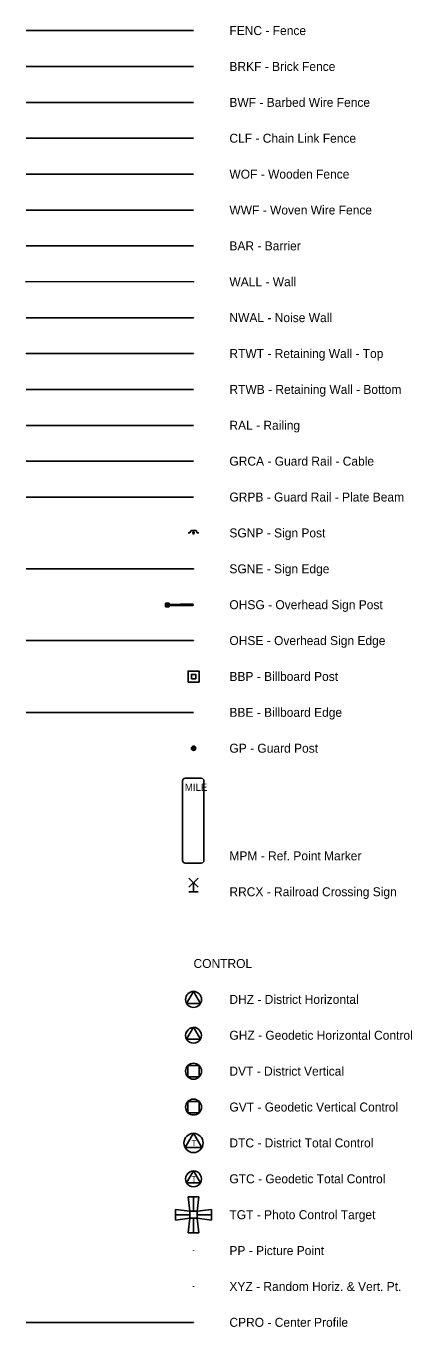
# Model space of a CAD drawing. Extents: x 2147712 to 2176316, y 2125036 to 2131746.
# Drawn here: x 2175974 to 2176297, y 2128230 to 2129318 of the extents above; entities that cross this region are included whole.
import ezdxf

# ---------------------------------------------------------------- set-up
doc = ezdxf.new("R2010")
doc.units = 0
for name, color, linetype in [('Default', 7, 'Continuous'), ('HORZ CTRL', 7, 'Continuous'), ('MANMD STRU INP', 7, 'Continuous'), ('PHO CTRL', 7, 'Continuous'), ('PNM MNMD STRU INP', 7, 'Continuous'), ('VERT CTRL', 7, 'Continuous')]:
    doc.layers.add(name, color=color, linetype=linetype)

msp = doc.modelspace()

# ---------------------------------------------------------------- linework, layer by layer
at = {"layer": 'HORZ CTRL'}
for p, q in [((2176114.2, 2128510.4), (2176108.4, 2128500.4)), ((2176120, 2128500.4), (2176114.2, 2128510.4)), ((2176108.4, 2128500.4), (2176120, 2128500.4)), ((2176114.2, 2128503.7), (2176114.2, 2128503.7)), ((2176114.2, 2128503.7), (2176114.2, 2128503.7)), ((2176114.2, 2128503.7), (2176114.2, 2128503.7)), ((2176114.2, 2128473.7), (2176114.2, 2128473.7)), ((2176114.2, 2128473.7), (2176114.2, 2128473.7)), ((2176114.2, 2128473.7), (2176114.2, 2128473.7)), ((2176114.1, 2128391.8), (2176107.2, 2128379.8)), ((2176121.1, 2128379.8), (2176114.1, 2128391.8)), ((2176107.2, 2128379.8), (2176121.1, 2128379.8)), ((2176114.1, 2128383.7), (2176114.1, 2128383.7)), ((2176114.1, 2128383.7), (2176114.1, 2128383.7)), ((2176114.1, 2128383.7), (2176114.1, 2128383.7)), ((2176114.2, 2128353.7), (2176114.2, 2128353.7)), ((2176114.2, 2128353.7), (2176114.2, 2128353.7)), ((2176114.2, 2128353.7), (2176114.2, 2128353.7))]:
    msp.add_line(p, q, dxfattribs=at)
for points in [[(2176114.2, 2128480.4), (2176108.4, 2128470.4)], [(2176120, 2128470.4), (2176114.2, 2128480.4)], [(2176108.4, 2128470.4), (2176120, 2128470.4)], [(2176108.4, 2128350.4), (2176114.2, 2128360.4)], [(2176114.2, 2128360.4), (2176120, 2128350.4)], [(2176108.4, 2128350.4), (2176120, 2128350.4)]]:
    msp.add_lwpolyline(points, dxfattribs=at)
for centre, radius in [((2176114.2, 2128503.7), 6.67), ((2176114.2, 2128383.7), 8)]:
    msp.add_circle(centre, radius, dxfattribs=at)
for centre, radius, start, end in [((2176114.4, 2128473.6), 6.78, 91.4546, 208.318), ((2176114, 2128473.6), 6.81, 332.0572, 88.1702), ((2176114.2, 2128473.9), 6.79, 211.3182, 328.6818), ((2176114.4, 2128353.6), 6.78, 91.4546, 208.318), ((2176114, 2128353.6), 6.81, 332.0572, 88.1702), ((2176114.2, 2128353.9), 6.79, 211.3182, 328.6818)]:
    msp.add_arc(centre, radius, start, end, dxfattribs=at)
at = {"layer": 'MANMD STRU INP'}
for p, q in [((2176114.2, 2129313.7), (2175974.2, 2129313.7)), ((2176114.2, 2129283.7), (2175974.2, 2129283.7)), ((2176114.2, 2129253.7), (2175974.2, 2129253.7)), ((2175974.2, 2129223.7), (2176114.2, 2129223.7)), ((2176114.2, 2129193.7), (2175974.2, 2129193.7)), ((2175974.2, 2129163.7), (2176114.2, 2129163.7)), ((2176114.2, 2129133.7), (2175974.2, 2129133.7)), ((2176114.2, 2129103.7), (2175974.3, 2129103.9)), ((2176114.2, 2129073.7), (2175974.3, 2129073.7)), ((2176114.2, 2129043.7), (2175974.2, 2129043.9)), ((2176114.2, 2129013.7), (2175974.4, 2129013.7)), ((2176114.2, 2128983.7), (2175974.2, 2128983.7)), ((2176114.2, 2128953.7), (2175974.2, 2128953.7)), ((2176114.2, 2128923.7), (2175974.2, 2128923.7)), ((2176109.8, 2128893.7), (2176111.2, 2128893.7)), ((2176111.2, 2128893.7), (2176112.2, 2128895.8)), ((2176112.2, 2128895.8), (2176116.3, 2128895.8)), ((2176113, 2128893.7), (2176114.2, 2128893.7)), ((2176114.2, 2128895), (2176114.2, 2128893.7)), ((2176114.2, 2128893.7), (2176114.2, 2128892.4)), ((2176114.2, 2128893.7), (2176115.4, 2128893.7)), ((2176116.3, 2128895.8), (2176117.2, 2128893.7)), ((2176117.2, 2128893.7), (2176118.6, 2128893.7)), ((2176114.2, 2128863.7), (2175974.2, 2128863.7)), ((2176114.1, 2128863.5), (2176114.3, 2128863.9)), ((2176114.1, 2128863.9), (2176114.3, 2128863.5)), ((2176090.8, 2128835), (2176090.8, 2128832)), ((2176090.8, 2128835), (2176093.8, 2128835)), ((2176093.8, 2128835), (2176093.8, 2128832)), ((2176093.8, 2128832), (2176090.8, 2128832)), ((2176092.3, 2128833.8), (2176113.9, 2128833.8)), ((2176092.3, 2128833.5), (2176092.3, 2128833.5)), ((2176092.3, 2128833.2), (2176113.9, 2128833.2)), ((2176103.4, 2128834.1), (2176113.9, 2128834.1)), ((2176113.9, 2128833.8), (2176113.9, 2128833.2)), ((2176114.2, 2128803.7), (2175974.2, 2128803.7)), ((2176114.1, 2128803.5), (2176114.3, 2128803.9)), ((2176114.1, 2128803.9), (2176114.3, 2128803.5)), ((2176114.2, 2128773.7), (2176114.2, 2128773.7)), ((2176114.2, 2128773.7), (2176114.2, 2128773.7)), ((2176114.2, 2128743.7), (2175974.2, 2128743.7)), ((2176104.9, 2128686.3), (2176104.9, 2128619.9)), ((2176120.7, 2128688.6), (2176107.2, 2128688.6)), ((2176122.9, 2128619.9), (2176122.9, 2128686.3)), ((2176107.2, 2128617.6), (2176120.7, 2128617.6)), ((2176110.3, 2128605.1), (2176118.1, 2128597.6)), ((2176110.3, 2128597.6), (2176118.1, 2128605.1)), ((2176114.2, 2128593.7), (2176114.2, 2128601.2)), ((2176110.3, 2128593.7), (2176118.1, 2128593.7))]:
    msp.add_line(p, q, dxfattribs=at)
for points in [[(2176109.7, 2128769.1), (2176109.7, 2128778.2), (2176118.8, 2128778.2), (2176118.8, 2128769.1)], [(2176112.5, 2128771.9), (2176112.5, 2128775.4), (2176116, 2128775.4), (2176116, 2128771.9)]]:
    msp.add_lwpolyline(points, close=True, dxfattribs=at)
for centre, radius in [((2176092.3, 2128833.5), 1.2), ((2176092.3, 2128833.5), 0.3), ((2176114.3, 2128713.7), 1.83), ((2176114.3, 2128713.7), 1.35), ((2176114.3, 2128713.7), 0.794)]:
    msp.add_circle(centre, radius, dxfattribs=at)
for centre, start, end in [((2176107.2, 2128686.4), 90, 180), ((2176120.7, 2128686.4), 0, 90), ((2176107.2, 2128620), 180, 270), ((2176120.7, 2128620), 270, 360)]:
    msp.add_arc(centre, 2.25, start, end, dxfattribs=at)
at = {"layer": 'PHO CTRL'}
for p, q in [((2176109.7, 2128338.7), (2176114.2, 2128338.7)), ((2176109.7, 2128338.7), (2176111.2, 2128326.7)), ((2176114.2, 2128326.7), (2176114.2, 2128338.7)), ((2176114.2, 2128338.7), (2176118.7, 2128338.7)), ((2176118.7, 2128338.7), (2176117.2, 2128326.7)), ((2176099.2, 2128323.7), (2176099.2, 2128328.2)), ((2176099.2, 2128328.2), (2176111.2, 2128326.7)), ((2176099.2, 2128319.2), (2176099.2, 2128323.7)), ((2176111.2, 2128323.7), (2176099.2, 2128323.7)), ((2176111.2, 2128323.7), (2176111.2, 2128326.7)), ((2176117.2, 2128326.7), (2176111.2, 2128326.7)), ((2176111.2, 2128320.7), (2176111.2, 2128323.7)), ((2176114.2, 2128323.7), (2176114.2, 2128323.7)), ((2176129.2, 2128328.2), (2176117.2, 2128326.7)), ((2176117.2, 2128323.7), (2176117.2, 2128326.7)), ((2176117.2, 2128320.7), (2176117.2, 2128323.7)), ((2176129.2, 2128323.7), (2176117.2, 2128323.7)), ((2176129.2, 2128323.7), (2176129.2, 2128328.2)), ((2176129.2, 2128319.2), (2176129.2, 2128323.7)), ((2176099.2, 2128319.2), (2176111.2, 2128320.7)), ((2176111.2, 2128320.7), (2176109.7, 2128308.7)), ((2176117.2, 2128320.7), (2176111.2, 2128320.7)), ((2176114.2, 2128308.7), (2176114.2, 2128320.7)), ((2176129.2, 2128319.2), (2176117.2, 2128320.7)), ((2176117.2, 2128320.7), (2176118.7, 2128308.7)), ((2176109.7, 2128308.7), (2176114.2, 2128308.7)), ((2176114.2, 2128308.7), (2176118.7, 2128308.7)), ((2176114.1, 2128293.5), (2176114.3, 2128293.9)), ((2176114.1, 2128293.9), (2176114.3, 2128293.5)), ((2176114.1, 2128263.5), (2176114.3, 2128263.9)), ((2176114.1, 2128263.9), (2176114.3, 2128263.5)), ((2176114.2, 2128233.7), (2175974.2, 2128233.7)), ((2176114.1, 2128233.5), (2176114.3, 2128233.9)), ((2176114.1, 2128233.9), (2176114.3, 2128233.5))]:
    msp.add_line(p, q, dxfattribs=at)
at = {"layer": 'PNM MNMD STRU INP'}
for p, q in [((2175974.1, 2129103.5), (2175974.3, 2129103.9)), ((2175974.1, 2129103.9), (2175974.3, 2129103.5)), ((2176114.1, 2129103.5), (2176114.3, 2129103.9)), ((2176114.1, 2129103.9), (2176114.3, 2129103.5)), ((2176114.1, 2129073.5), (2176114.3, 2129073.9)), ((2176114.1, 2129073.9), (2176114.3, 2129073.5)), ((2175974.2, 2129043.5), (2175974.4, 2129043.9)), ((2175974.2, 2129043.9), (2175974.4, 2129043.5)), ((2176114.1, 2129043.5), (2176114.3, 2129043.9)), ((2176114.1, 2129043.9), (2176114.3, 2129043.5))]:
    msp.add_line(p, q, dxfattribs=at)
at = {"layer": 'VERT CTRL'}
for p, q in [((2176114.2, 2128443.7), (2176114.2, 2128443.7)), ((2176114.2, 2128443.7), (2176114.2, 2128443.7)), ((2176114.2, 2128413.7), (2176114.2, 2128413.7)), ((2176114.2, 2128413.7), (2176114.2, 2128413.7))]:
    msp.add_line(p, q, dxfattribs=at)
msp.add_lwpolyline([(2176109.5, 2128439), (2176109.5, 2128448.4), (2176118.9, 2128448.4), (2176118.9, 2128439)], close=True, dxfattribs=at)
for points in [[(2176118.9, 2128418.4), (2176109.4, 2128418.4)], [(2176109.4, 2128418.4), (2176109.4, 2128409)], [(2176118.9, 2128418.4), (2176118.9, 2128418.4)], [(2176118.9, 2128418.4), (2176118.9, 2128409)], [(2176118.9, 2128409), (2176109.4, 2128409)]]:
    msp.add_lwpolyline(points, dxfattribs=at)
msp.add_circle((2176114.2, 2128443.7), 6.67, dxfattribs=at)
for centre, radius, start, end in [((2176114.3, 2128413.7), 6.74, 135.7573, 224.2427), ((2176114.2, 2128413.5), 6.82, 45.8526, 134.1474), ((2176114, 2128413.7), 6.85, 316.6405, 43.3595), ((2176114.2, 2128414), 6.87, 226.2206, 313.7794)]:
    msp.add_arc(centre, radius, start, end, dxfattribs=at)

# ---------------------------------------------------------------- texts
at = {"layer": 'Default'}
for s, p in [('FENC - Fence', (2176144.2, 2129310)), ('BRKF - Brick Fence', (2176144.2, 2129280)), ('BWF - Barbed Wire Fence', (2176144.2, 2129250)), ('CLF - Chain Link Fence', (2176144.2, 2129220)), ('WOF - Wooden Fence', (2176144.2, 2129190)), ('WWF - Woven Wire Fence', (2176144.2, 2129160)), ('BAR - Barrier', (2176144.2, 2129130)), ('WALL - Wall', (2176144.2, 2129100)), ('NWAL - Noise Wall', (2176144.2, 2129070)), ('RTWT - Retaining Wall - Top', (2176144.2, 2129040)), ('RTWB - Retaining Wall - Bottom', (2176144.2, 2129010)), ('RAL - Railing', (2176144.2, 2128980)), ('GRCA - Guard Rail - Cable', (2176144.2, 2128950)), ('GRPB - Guard Rail - Plate Beam', (2176144.2, 2128920)), ('SGNP - Sign Post', (2176144.2, 2128890)), ('SGNE - Sign Edge', (2176144.2, 2128860)), ('OHSG - Overhead Sign Post', (2176144.2, 2128830)), ('OHSE - Overhead Sign Edge', (2176144.2, 2128800)), ('BBP - Billboard Post', (2176144.2, 2128770)), ('BBE - Billboard Edge', (2176144.2, 2128740)), ('GP - Guard Post', (2176144.2, 2128710)), ('MPM - Ref. Point Marker', (2176144.2, 2128620)), ('RRCX - Railroad Crossing Sign', (2176144.2, 2128590)), ('CONTROL', (2176114.2, 2128530)), ('DHZ - District Horizontal', (2176144.2, 2128500)), ('GHZ - Geodetic Horizontal Control', (2176144.2, 2128470)), ('DVT - District Vertical', (2176144.2, 2128440)), ('GVT - Geodetic Vertical Control', (2176144.2, 2128410)), ('DTC - District Total Control', (2176144.2, 2128380)), ('GTC - Geodetic Total Control', (2176144.2, 2128350)), ('TGT - Photo Control Target', (2176144.2, 2128320)), ('PP - Picture Point', (2176144.2, 2128290)), ('XYZ - Random Horiz. & Vert. Pt.', (2176144.2, 2128260)), ('CPRO - Center Profile', (2176144.2, 2128230))]:
    msp.add_text(s, height=7.5, dxfattribs=at).set_placement(p)
at = {"layer": 'HORZ CTRL'}
for p in [(2176112.6, 2128381.2), (2176112.6, 2128351.2)]:
    msp.add_text('T', height=5, dxfattribs=at).set_placement(p)
at = {"layer": 'MANMD STRU INP'}
msp.add_text('MILE', height=6.03, dxfattribs=at).set_placement((2176106.9, 2128678.1))

doc.saveas('drawing.dxf')
